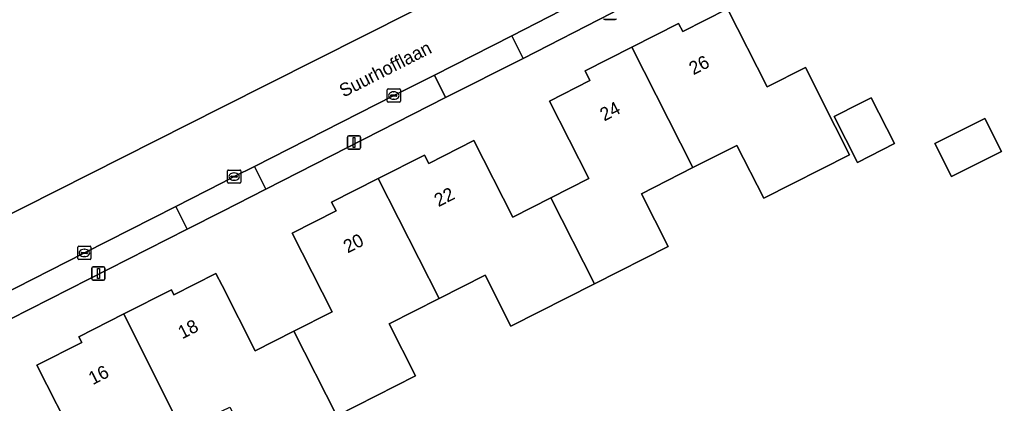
# Model space of a CAD drawing. Extents: x 162722 to 165104, y 384719 to 386284.
# Drawn here: x 163984.7 to 164059, y 385107.7 to 385136.7 of the extents above; entities that cross this region are included whole.
import ezdxf

# ---------------------------------------------------------------- set-up
doc = ezdxf.new("R2010")
doc.units = 0
for name, color, linetype in [('IMGEO_Erf', 7, 'Continuous'), ('IMGEO_Kolk', 7, 'Continuous'), ('IMGEO_Lichtmast', 7, 'Continuous'), ('IMGEO_Openbare_ruimte_label', 7, 'Continuous'), ('IMGEO_Pand', 7, 'Continuous'), ('IMGEO_Pand_nummerreeks', 7, 'Continuous'), ('IMGEO_Rijbaan_lokaal_gesloten', 7, 'Continuous'), ('IMGEO_Voetpad_open', 7, 'Continuous')]:
    doc.layers.add(name, color=color, linetype=linetype)

msp = doc.modelspace()

# ---------------------------------------------------------------- linework, layer by layer
at = {"layer": 'IMGEO_Erf'}
for points in [[(163964.943, 385112.381), (164000, 385130.066), (164025.009, 385142.682)], [(164030.99, 385137.973), (164029.497, 385137.184), (164022.8, 385133.757), (164016.911, 385130.797), (164003.318, 385123.864), (164000, 385122.177), (163997.359, 385120.835), (163983.951, 385114.019)], [(163988.982, 385104.661), (163985.985, 385110.551), (163989.373, 385112.275), (163989.162, 385112.69), (163992.563, 385114.421), (163996.163, 385116.253), (163996.358, 385115.871), (163999.532, 385117.486), (164000, 385116.568), (164002.516, 385111.63), (164005.438, 385113.111), (164008.332, 385114.578), (164005.312, 385120.535), (164008.629, 385122.217), (164008.297, 385122.872), (164011.821, 385124.659), (164015.335, 385126.44), (164015.656, 385125.808), (164019.076, 385127.542), (164022.011, 385121.753), (164024.888, 385123.212), (164027.759, 385124.668), (164024.792, 385130.521), (164027.859, 385132.076), (164027.488, 385132.809), (164031.033, 385134.606), (164034.573, 385136.401), (164034.886, 385135.784), (164038.282, 385137.505), (164041.28, 385131.592), (164044.171, 385133.058), (164046.431, 385128.599), (164047.513, 385126.465), (164041.012, 385123.168), (164038.981, 385127.174), (164035.656, 385125.488), (164031.747, 385123.506), (164033.767, 385119.521), (164028.196, 385116.697), (164021.876, 385113.493), (164019.918, 385117.354), (164016.428, 385115.584), (164012.664, 385113.676), (164014.655, 385109.747), (164008.68, 385106.718)]]:
    msp.add_lwpolyline(points, dxfattribs=at)
for points in [[(164048.108, 385125.881), (164046.351, 385129.349), (164048.302, 385130.338), (164049.159, 385130.773), (164050.917, 385127.305)], [(164059.006, 385126.714), (164055.219, 385124.822), (164053.972, 385127.317), (164057.759, 385129.209)]]:
    msp.add_lwpolyline(points, close=True, dxfattribs=at)
at = {"layer": 'IMGEO_Kolk'}
for p, q in [((164012.504, 385130.516), (164012.504, 385131.368)), ((164012.579, 385131.442), (164013.431, 385131.442)), ((164012.992, 385131.222), (164013.017, 385131.222)), ((164013.505, 385131.368), (164013.505, 385130.516)), ((164012.763, 385130.936), (164012.763, 385130.948)), ((164013.201, 385130.899), (164012.803, 385130.899)), ((164012.806, 385130.985), (164013.204, 385130.985)), ((164013.015, 385130.662), (164012.99, 385130.662)), ((164013.247, 385130.948), (164013.247, 385130.936)), ((164013.431, 385130.442), (164012.579, 385130.442)), ((164000.49, 385125.31), (164001.342, 385125.31)), ((164000.415, 385124.384), (164000.415, 385125.236)), ((164000.674, 385124.804), (164000.674, 385124.816)), ((164001.112, 385124.767), (164000.714, 385124.767)), ((164000.717, 385124.853), (164001.115, 385124.853)), ((164000.926, 385124.53), (164000.901, 385124.53)), ((164000.903, 385125.09), (164000.928, 385125.09)), ((164001.158, 385124.816), (164001.158, 385124.804)), ((164001.416, 385125.236), (164001.416, 385124.384)), ((164001.342, 385124.31), (164000.49, 385124.31)), ((163989.076, 385118.612), (163989.076, 385119.464)), ((163989.151, 385119.538), (163990.003, 385119.538)), ((163989.564, 385119.318), (163989.589, 385119.318)), ((163990.077, 385119.464), (163990.077, 385118.612)), ((163989.335, 385119.032), (163989.335, 385119.044)), ((163989.773, 385118.995), (163989.375, 385118.995)), ((163989.378, 385119.081), (163989.776, 385119.081)), ((163989.587, 385118.758), (163989.562, 385118.758)), ((163989.819, 385119.044), (163989.819, 385119.032)), ((163990.003, 385118.538), (163989.151, 385118.538))]:
    msp.add_line(p, q, dxfattribs=at)
for points in [[(164012.504, 385130.516), (164012.504, 385131.368)], [(164012.579, 385131.442), (164013.431, 385131.442)], [(164013.505, 385131.368), (164013.505, 385130.516)], [(164013.431, 385130.442), (164012.579, 385130.442)], [(164000.49, 385125.31), (164001.342, 385125.31)], [(164000.415, 385124.384), (164000.415, 385125.236)], [(164001.416, 385125.236), (164001.416, 385124.384)], [(164001.342, 385124.31), (164000.49, 385124.31)], [(163989.076, 385118.612), (163989.076, 385119.464)], [(163989.151, 385119.538), (163990.003, 385119.538)], [(163990.077, 385119.464), (163990.077, 385118.612)], [(163990.003, 385118.538), (163989.151, 385118.538)]]:
    msp.add_lwpolyline(points, dxfattribs=at)
for centre, radius, start, end in [((164012.581, 385131.366), 0.0765, 91.55205, 178.44795), ((164012.581, 385131.366), 0.0765, 91.55205, 178.44795), ((164013.429, 385131.366), 0.0765, 1.55205, 88.44795), ((164013.429, 385131.366), 0.0765, 1.55205, 88.44795), ((164012.581, 385130.518), 0.0765, 181.55205, 268.44795), ((164012.581, 385130.518), 0.0765, 181.55205, 268.44795), ((164012.803, 385130.945), 0.0403, 85.87752, 175.75265), ((164012.8, 385130.935), 0.0366, 178.93798, 274.71019), ((164013.204, 385130.942), 0.043, 264.86636, 352.45326), ((164013.208, 385130.947), 0.0386, 1.73085, 96.63898), ((164013.429, 385130.518), 0.0765, 271.55205, 358.44795), ((164013.429, 385130.518), 0.0765, 271.55205, 358.44795), ((164000.492, 385125.234), 0.0765, 91.55205, 178.44795), ((164000.492, 385125.234), 0.0765, 91.55205, 178.44795), ((164001.34, 385125.234), 0.0765, 1.55205, 88.44795), ((164001.34, 385125.234), 0.0765, 1.55205, 88.44795), ((164000.714, 385124.813), 0.0403, 85.87752, 175.75265), ((164000.711, 385124.803), 0.0366, 178.93798, 274.71019), ((164001.115, 385124.81), 0.043, 264.86636, 352.45326), ((164001.119, 385124.815), 0.0386, 1.73085, 96.63898), ((164000.492, 385124.386), 0.0765, 181.55205, 268.44795), ((164000.492, 385124.386), 0.0765, 181.55205, 268.44795), ((164001.34, 385124.386), 0.0765, 271.55205, 358.44795), ((164001.34, 385124.386), 0.0765, 271.55205, 358.44795), ((163989.153, 385119.462), 0.0765, 91.55205, 178.44795), ((163989.153, 385119.462), 0.0765, 91.55205, 178.44795), ((163990.001, 385119.462), 0.0765, 1.55205, 88.44795), ((163990.001, 385119.462), 0.0765, 1.55205, 88.44795), ((163989.153, 385118.614), 0.0765, 181.55205, 268.44795), ((163989.153, 385118.614), 0.0765, 181.55205, 268.44795), ((163989.375, 385119.041), 0.0403, 85.87752, 175.75265), ((163989.372, 385119.031), 0.0366, 178.93798, 274.71019), ((163989.776, 385119.038), 0.043, 264.86636, 352.45326), ((163989.78, 385119.043), 0.0386, 1.73085, 96.63898), ((163990.001, 385118.614), 0.0765, 271.55205, 358.44795), ((163990.001, 385118.614), 0.0765, 271.55205, 358.44795)]:
    msp.add_arc(centre, radius, start, end, dxfattribs=at)
for centre, major_axis, ratio, start_param, end_param in [((164012.991, 385130.942), (-0.387, 0.002), 0.722429, 4.712389, 7.853982), ((164013.016, 385130.942), (-0.39, 0.002), 0.717154, 1.570796, 4.712389), ((164000.902, 385124.81), (-0.387, 0.002), 0.722429, 4.712389, 7.853982), ((164000.927, 385124.81), (-0.39, 0.002), 0.717154, 1.570796, 4.712389), ((163989.563, 385119.038), (-0.387, 0.002), 0.722429, 4.712389, 7.853982), ((163989.588, 385119.038), (-0.39, 0.002), 0.717154, 1.570796, 4.712389)]:
    msp.add_ellipse(centre, major_axis=major_axis, ratio=ratio, start_param=start_param, end_param=end_param, dxfattribs=at)
at = {"layer": 'IMGEO_Lichtmast'}
for p, q in [((164029.773, 385136.683), (164028.983, 385136.683)), ((164028.983, 385136.683), (164029.773, 385136.683)), ((164009.496, 385126.996), (164009.496, 385127.796)), ((164009.496, 385127.796), (164009.496, 385126.996)), ((164009.596, 385127.896), (164010.386, 385127.896)), ((164010.386, 385127.896), (164009.596, 385127.896)), ((164010.486, 385127.796), (164010.486, 385126.996)), ((164010.486, 385126.996), (164010.486, 385127.796)), ((164010.386, 385126.896), (164009.596, 385126.896)), ((164009.596, 385126.896), (164010.386, 385126.896)), ((163990.146, 385117.079), (163990.146, 385117.879)), ((163990.146, 385117.879), (163990.146, 385117.079)), ((163990.246, 385117.979), (163991.036, 385117.979)), ((163991.036, 385117.979), (163990.246, 385117.979)), ((163991.136, 385117.879), (163991.136, 385117.079)), ((163991.136, 385117.079), (163991.136, 385117.879)), ((163991.036, 385116.979), (163990.246, 385116.979)), ((163990.246, 385116.979), (163991.036, 385116.979))]:
    msp.add_line(p, q, dxfattribs=at)
for points in [[(164009.916, 385127.771), (164010.066, 385127.771), (164010.066, 385127.021), (164009.916, 385127.021), (164009.916, 385127.771)], [(163990.566, 385117.854), (163990.716, 385117.854), (163990.716, 385117.104), (163990.566, 385117.104), (163990.566, 385117.854)]]:
    msp.add_lwpolyline(points, dxfattribs=at)
for centre, start, end in [((164028.983, 385136.783), 180, 270), ((164028.983, 385136.783), 180, 270), ((164029.773, 385136.783), 270, 0), ((164029.773, 385136.783), 270, 0), ((164009.596, 385127.796), 90, 180), ((164009.596, 385127.796), 90, 180), ((164010.386, 385127.796), 0, 90), ((164010.386, 385127.796), 360, 90), ((164009.596, 385126.996), 180, 270), ((164009.596, 385126.996), 180, 270), ((164010.386, 385126.996), 270, 0), ((164010.386, 385126.996), 270, 0), ((163990.246, 385117.879), 90, 180), ((163990.246, 385117.879), 90, 180), ((163991.036, 385117.879), 0, 90), ((163991.036, 385117.879), 360, 90), ((163990.246, 385117.079), 180, 270), ((163990.246, 385117.079), 180, 270), ((163991.036, 385117.079), 270, 0), ((163991.036, 385117.079), 270, 0)]:
    msp.add_arc(centre, 0.1, start, end, dxfattribs=at)
at = {"layer": 'IMGEO_Pand'}
for points in [[(164035.656, 385125.488), (164038.981, 385127.174), (164041.012, 385123.168), (164047.513, 385126.465), (164046.431, 385128.599), (164044.171, 385133.058), (164041.28, 385131.592), (164038.282, 385137.505), (164034.886, 385135.784), (164034.573, 385136.401), (164031.033, 385134.606)], [(164031.033, 385134.606), (164027.488, 385132.809), (164027.859, 385132.076), (164024.792, 385130.521), (164027.759, 385124.668), (164024.888, 385123.212), (164028.196, 385116.697), (164033.767, 385119.521), (164031.747, 385123.506), (164035.656, 385125.488)], [(164046.351, 385129.349), (164048.108, 385125.881), (164050.917, 385127.305), (164049.159, 385130.773), (164048.302, 385130.338)], [(164059.006, 385126.714), (164057.759, 385129.209), (164053.972, 385127.317), (164055.219, 385124.822)], [(164016.428, 385115.584), (164019.918, 385117.354), (164021.876, 385113.493), (164028.196, 385116.697), (164024.888, 385123.212), (164022.011, 385121.753), (164019.076, 385127.542), (164015.656, 385125.808), (164015.335, 385126.44), (164011.821, 385124.659)], [(164011.821, 385124.659), (164008.297, 385122.872), (164008.629, 385122.217), (164005.312, 385120.535), (164008.332, 385114.578), (164005.438, 385113.111), (164008.68, 385106.718), (164014.655, 385109.747), (164012.664, 385113.676), (164016.428, 385115.584)], [(163997.032, 385105.471), (164000, 385107.103), (164000.578, 385107.378), (164002.501, 385103.585), (164008.68, 385106.718), (164005.438, 385113.111), (164002.516, 385111.63), (164000, 385116.568), (163999.532, 385117.486), (163996.358, 385115.871), (163996.163, 385116.253), (163992.563, 385114.421)], [(163992.563, 385114.421), (163989.162, 385112.69), (163989.373, 385112.275), (163985.985, 385110.551), (163988.982, 385104.661), (163986.206, 385103.248), (163989.429, 385096.827), (163995.314, 385099.822), (163993.443, 385103.498), (163997.032, 385105.471)]]:
    msp.add_lwpolyline(points, close=True, dxfattribs=at)
at = {"layer": 'IMGEO_Rijbaan_lokaal_gesloten'}
for points in [[(164025.009, 385142.682), (164000, 385130.066), (163964.943, 385112.381), (163967.315, 385107.723), (163976.438, 385112.369), (163976.92, 385112.606), (163983.085, 385115.734), (163989.577, 385119.038), (163996.493, 385122.545), (164000, 385124.341), (164000.916, 385124.81), (164002.466, 385125.576), (164013.005, 385130.942)], [(164013.005, 385130.942), (164016.077, 385132.488), (164021.941, 385135.467), (164026.599, 385137.858), (164029.39, 385139.278)]]:
    msp.add_lwpolyline(points, dxfattribs=at)
at = {"layer": 'IMGEO_Voetpad_open'}
msp.add_lwpolyline([(164029.39, 385139.278), (164026.599, 385137.858), (164021.941, 385135.467), (164022.8, 385133.757), (164029.497, 385137.184), (164030.99, 385137.973)], dxfattribs=at)
for points in [[(164021.941, 385135.467), (164016.077, 385132.488), (164016.911, 385130.797), (164022.8, 385133.757)], [(164016.077, 385132.488), (164013.005, 385130.942), (164002.466, 385125.576), (164003.318, 385123.864), (164016.911, 385130.797)], [(164002.466, 385125.576), (164000.916, 385124.81), (164000, 385124.341), (163996.493, 385122.545), (163997.359, 385120.835), (164000, 385122.177), (164003.318, 385123.864)], [(163996.493, 385122.545), (163989.577, 385119.038), (163983.085, 385115.734), (163983.951, 385114.019), (163997.359, 385120.835)]]:
    msp.add_lwpolyline(points, close=True, dxfattribs=at)

# ---------------------------------------------------------------- texts
at = {"layer": 'IMGEO_Openbare_ruimte_label'}
msp.add_text('Suurhofflaan', height=1, rotation=26.87254, dxfattribs=at).set_placement((164009.2, 385130.783))
at = {"layer": 'IMGEO_Pand_nummerreeks'}
for s, rotation, p in [('26', 27.37136, (164035.684, 385132.467)), ('24', 27.37136, (164028.939, 385128.975)), ('22', 26.97981, (164016.385, 385122.491)), ('20', 26.97981, (164009.508, 385118.99)), ('18', 27.10888, (163996.988, 385112.499)), ('16', 27.10888, (163990.212, 385109.03))]:
    msp.add_text(s, height=1, rotation=rotation, dxfattribs=at).set_placement(p)

doc.saveas('drawing.dxf')
